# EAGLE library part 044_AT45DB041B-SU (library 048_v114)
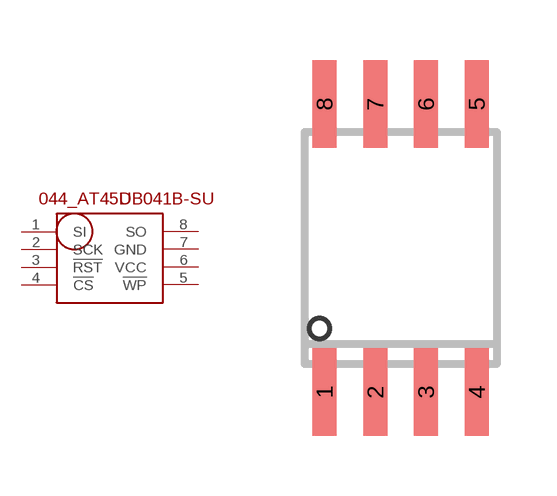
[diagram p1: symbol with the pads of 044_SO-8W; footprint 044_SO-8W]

Designator prefix -

## 044_AT45DB041B-SU  [044_SO-8W]
1  SI
2  SCK
3  !RST
4  !CS
5  !WP
6  VCC  pwr
7  GND  pwr
8  SO

## Footprint 044_SO-8W (pad centres in mm)
smd 0.6 x 2.2: 1 0.095,0.9; 2 1.365,0.9; 3 2.635,0.9; 4 3.905,0.9; 5 3.905,8.1; 6 2.635,8.1; 7 1.365,8.1; 8 0.095,8.1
